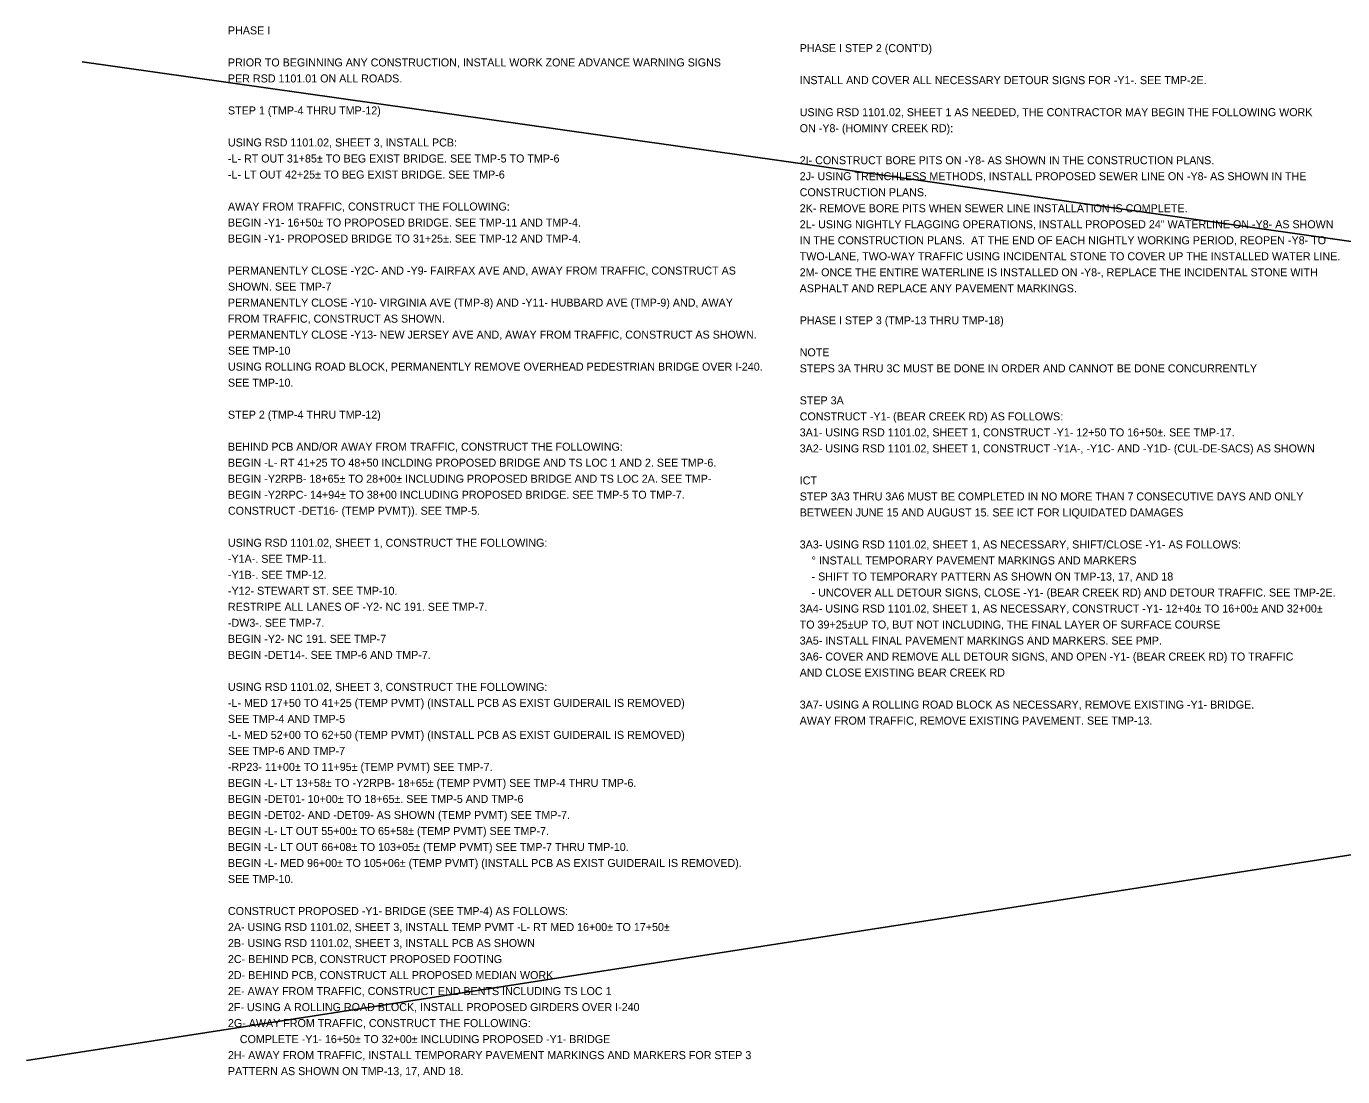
# Model space of a CAD drawing. Extents: x 2483905 to 2494512, y 366160 to 372330.
# Drawn here: x 2486863 to 2488014, y 371409 to 372328 of the extents above; entities that cross this region are included whole.
import ezdxf

# ---------------------------------------------------------------- set-up
doc = ezdxf.new("R2010")
doc.units = 0
doc.layers.add('TC SHEET BORDER LINE THIN', color=7, linetype='Continuous')

msp = doc.modelspace()

# ---------------------------------------------------------------- linework, layer by layer
at = {"layer": 'TC SHEET BORDER LINE THIN'}
for p, q in [((2486912.1, 372296.4), (2492000.8, 371577)), ((2486863.2, 371423.3), (2492035.7, 372226.5))]:
    msp.add_line(p, q, dxfattribs=at)

# ---------------------------------------------------------------- texts
for s, p in [('PHASE I', (2487039.5, 372320.5)), ("PHASE I STEP 2 (CONT'D)", (2487539.5, 372305)), ('PRIOR TO BEGINNING ANY CONSTRUCTION, INSTALL WORK ZONE ADVANCE WARNING SIGNS', (2487039.5, 372292.5)), ('PER RSD 1101.01 ON ALL ROADS.', (2487039.5, 372278.5)), ('INSTALL AND COVER ALL NECESSARY DETOUR SIGNS FOR -Y1-. SEE TMP-2E.', (2487539.5, 372277)), ('STEP 1 (TMP-4 THRU TMP-12)', (2487039.5, 372250.5)), ('USING RSD 1101.02, SHEET 1 AS NEEDED, THE CONTRACTOR MAY BEGIN THE FOLLOWING WORK', (2487539.5, 372249)), ('ON -Y8- (HOMINY CREEK RD):', (2487539.5, 372235)), ('USING RSD 1101.02, SHEET 3, INSTALL PCB:', (2487039.5, 372222.5)), ('-L- RT OUT 31+85± TO BEG EXIST BRIDGE. SEE TMP-5 TO TMP-6', (2487039.5, 372208.5)), ('2I- CONSTRUCT BORE PITS ON -Y8- AS SHOWN IN THE CONSTRUCTION PLANS.', (2487539.5, 372207)), ('-L- LT OUT 42+25± TO BEG EXIST BRIDGE. SEE TMP-6', (2487039.5, 372194.5)), ('2J- USING TRENCHLESS METHODS, INSTALL PROPOSED SEWER LINE ON -Y8- AS SHOWN IN THE', (2487539.5, 372193)), ('CONSTRUCTION PLANS.', (2487539.5, 372179)), ('AWAY FROM TRAFFIC, CONSTRUCT THE FOLLOWING:', (2487039.5, 372166.5)), ('2K- REMOVE BORE PITS WHEN SEWER LINE INSTALLATION IS COMPLETE.', (2487539.5, 372165)), ('BEGIN -Y1- 16+50± TO PROPOSED BRIDGE. SEE TMP-11 AND TMP-4.', (2487039.5, 372152.5)), ('2L- USING NIGHTLY FLAGGING OPERATIONS, INSTALL PROPOSED 24" WATERLINE ON -Y8- AS SHOWN', (2487539.5, 372151)), ('BEGIN -Y1- PROPOSED BRIDGE TO 31+25±. SEE TMP-12 AND TMP-4.', (2487039.5, 372138.5)), ('IN THE CONSTRUCTION PLANS.  AT THE END OF EACH NIGHTLY WORKING PERIOD, REOPEN -Y8- TO', (2487539.5, 372137)), ('TWO-LANE, TWO-WAY TRAFFIC USING INCIDENTAL STONE TO COVER UP THE INSTALLED WATER LINE.', (2487539.5, 372123)), ('PERMANENTLY CLOSE -Y2C- AND -Y9- FAIRFAX AVE AND, AWAY FROM TRAFFIC, CONSTRUCT AS', (2487039.5, 372110.5)), ('2M- ONCE THE ENTIRE WATERLINE IS INSTALLED ON -Y8-, REPLACE THE INCIDENTAL STONE WITH', (2487539.5, 372109)), ('SHOWN. SEE TMP-7', (2487039.5, 372096.5)), ('ASPHALT AND REPLACE ANY PAVEMENT MARKINGS.', (2487539.5, 372095)), ('PERMANENTLY CLOSE -Y10- VIRGINIA AVE (TMP-8) AND -Y11- HUBBARD AVE (TMP-9) AND, AWAY', (2487039.5, 372082.5)), ('FROM TRAFFIC, CONSTRUCT AS SHOWN. ', (2487039.5, 372068.5)), ('PHASE I STEP 3 (TMP-13 THRU TMP-18)', (2487539.5, 372067)), ('PERMANENTLY CLOSE -Y13- NEW JERSEY AVE AND, AWAY FROM TRAFFIC, CONSTRUCT AS SHOWN.', (2487039.5, 372054.5)), ('SEE TMP-10', (2487039.5, 372040.5)), ('NOTE', (2487539.5, 372039)), ('USING ROLLING ROAD BLOCK, PERMANENTLY REMOVE OVERHEAD PEDESTRIAN BRIDGE OVER I-240.', (2487039.5, 372026.5)), ('STEPS 3A THRU 3C MUST BE DONE IN ORDER AND CANNOT BE DONE CONCURRENTLY', (2487539.5, 372025)), ('SEE TMP-10.', (2487039.5, 372012.5)), ('STEP 3A', (2487539.5, 371997)), ('STEP 2 (TMP-4 THRU TMP-12)', (2487039.5, 371984.5)), ('CONSTRUCT -Y1- (BEAR CREEK RD) AS FOLLOWS:', (2487539.5, 371983)), ('3A1- USING RSD 1101.02, SHEET 1, CONSTRUCT -Y1- 12+50 TO 16+50±. SEE TMP-17.', (2487539.5, 371969)), ('BEHIND PCB AND/OR AWAY FROM TRAFFIC, CONSTRUCT THE FOLLOWING:', (2487039.5, 371956.5)), ('3A2- USING RSD 1101.02, SHEET 1, CONSTRUCT -Y1A-, -Y1C- AND -Y1D- (CUL-DE-SACS) AS SHOWN', (2487539.5, 371955)), ('BEGIN -L- RT 41+25 TO 48+50 INCLDING PROPOSED BRIDGE AND TS LOC 1 AND 2. SEE TMP-6.', (2487039.5, 371942.5)), ('BEGIN -Y2RPB- 18+65± TO 28+00± INCLUDING PROPOSED BRIDGE AND TS LOC 2A. SEE TMP-', (2487039.5, 371928.5)), ('ICT', (2487539.5, 371927)), ('BEGIN -Y2RPC- 14+94± TO 38+00 INCLUDING PROPOSED BRIDGE. SEE TMP-5 TO TMP-7.', (2487039.5, 371914.5)), ('STEP 3A3 THRU 3A6 MUST BE COMPLETED IN NO MORE THAN 7 CONSECUTIVE DAYS AND ONLY', (2487539.5, 371913)), ('CONSTRUCT -DET16- (TEMP PVMT)). SEE TMP-5.', (2487039.5, 371900.5)), ('BETWEEN JUNE 15 AND AUGUST 15. SEE ICT FOR LIQUIDATED DAMAGES', (2487539.5, 371899)), ('USING RSD 1101.02, SHEET 1, CONSTRUCT THE FOLLOWING:', (2487039.5, 371872.5)), ('3A3- USING RSD 1101.02, SHEET 1, AS NECESSARY, SHIFT/CLOSE -Y1- AS FOLLOWS:', (2487539.5, 371871)), ('-Y1A-. SEE TMP-11.', (2487039.5, 371858.5)), ('    ° INSTALL TEMPORARY PAVEMENT MARKINGS AND MARKERS', (2487539.5, 371857)), ('-Y1B-. SEE TMP-12.', (2487039.5, 371844.5)), ('    - SHIFT TO TEMPORARY PATTERN AS SHOWN ON TMP-13, 17, AND 18', (2487539.5, 371843)), ('-Y12- STEWART ST. SEE TMP-10.', (2487039.5, 371830.5)), ('    - UNCOVER ALL DETOUR SIGNS, CLOSE -Y1- (BEAR CREEK RD) AND DETOUR TRAFFIC. SEE TMP-2E.', (2487539.5, 371829)), ('RESTRIPE ALL LANES OF -Y2- NC 191. SEE TMP-7.', (2487039.5, 371816.5)), ('3A4- USING RSD 1101.02, SHEET 1, AS NECESSARY, CONSTRUCT -Y1- 12+40± TO 16+00± AND 32+00±', (2487539.5, 371815)), ('-DW3-. SEE TMP-7.', (2487039.5, 371802.5)), ('TO 39+25±UP TO, BUT NOT INCLUDING, THE FINAL LAYER OF SURFACE COURSE', (2487539.5, 371801)), ('BEGIN -Y2- NC 191. SEE TMP-7', (2487039.5, 371788.5)), ('3A5- INSTALL FINAL PAVEMENT MARKINGS AND MARKERS. SEE PMP.', (2487539.5, 371787)), ('BEGIN -DET14-. SEE TMP-6 AND TMP-7.', (2487039.5, 371774.5)), ('3A6- COVER AND REMOVE ALL DETOUR SIGNS, AND OPEN -Y1- (BEAR CREEK RD) TO TRAFFIC', (2487539.5, 371773)), ('AND CLOSE EXISTING BEAR CREEK RD', (2487539.5, 371759)), ('USING RSD 1101.02, SHEET 3, CONSTRUCT THE FOLLOWING:', (2487039.5, 371746.5)), ('-L- MED 17+50 TO 41+25 (TEMP PVMT) (INSTALL PCB AS EXIST GUIDERAIL IS REMOVED)', (2487039.5, 371732.5)), ('3A7- USING A ROLLING ROAD BLOCK AS NECESSARY, REMOVE EXISTING -Y1- BRIDGE.', (2487539.5, 371731)), ('SEE TMP-4 AND TMP-5', (2487039.5, 371718.5)), ('AWAY FROM TRAFFIC, REMOVE EXISTING PAVEMENT. SEE TMP-13.', (2487539.5, 371717)), ('-L- MED 52+00 TO 62+50 (TEMP PVMT) (INSTALL PCB AS EXIST GUIDERAIL IS REMOVED)', (2487039.5, 371704.5)), ('SEE TMP-6 AND TMP-7', (2487039.5, 371690.5)), ('-RP23- 11+00± TO 11+95± (TEMP PVMT) SEE TMP-7.', (2487039.5, 371676.5)), ('BEGIN -L- LT 13+58± TO -Y2RPB- 18+65± (TEMP PVMT) SEE TMP-4 THRU TMP-6.', (2487039.5, 371662.5)), ('BEGIN -DET01- 10+00± TO 18+65±. SEE TMP-5 AND TMP-6', (2487039.5, 371648.5)), ('BEGIN -DET02- AND -DET09- AS SHOWN (TEMP PVMT) SEE TMP-7.', (2487039.5, 371634.5)), ('BEGIN -L- LT OUT 55+00± TO 65+58± (TEMP PVMT) SEE TMP-7.', (2487039.5, 371620.5)), ('BEGIN -L- LT OUT 66+08± TO 103+05± (TEMP PVMT) SEE TMP-7 THRU TMP-10.', (2487039.5, 371606.5)), ('BEGIN -L- MED 96+00± TO 105+06± (TEMP PVMT) (INSTALL PCB AS EXIST GUIDERAIL IS REMOVED).', (2487039.5, 371592.5)), ('SEE TMP-10.', (2487039.5, 371578.5)), ('CONSTRUCT PROPOSED -Y1- BRIDGE (SEE TMP-4) AS FOLLOWS:', (2487039.5, 371550.5)), ('2A- USING RSD 1101.02, SHEET 3, INSTALL TEMP PVMT -L- RT MED 16+00± TO 17+50±', (2487039.5, 371536.5)), ('2B- USING RSD 1101.02, SHEET 3, INSTALL PCB AS SHOWN', (2487039.5, 371522.5)), ('2C- BEHIND PCB, CONSTRUCT PROPOSED FOOTING', (2487039.5, 371508.5)), ('2D- BEHIND PCB, CONSTRUCT ALL PROPOSED MEDIAN WORK', (2487039.5, 371494.5)), ('2E- AWAY FROM TRAFFIC, CONSTRUCT END BENTS INCLUDING TS LOC 1', (2487039.5, 371480.5)), ('2F- USING A ROLLING ROAD BLOCK, INSTALL PROPOSED GIRDERS OVER I-240', (2487039.5, 371466.5)), ('2G- AWAY FROM TRAFFIC, CONSTRUCT THE FOLLOWING:', (2487039.5, 371452.5)), ('    COMPLETE -Y1- 16+50± TO 32+00± INCLUDING PROPOSED -Y1- BRIDGE', (2487039.5, 371438.5)), ('2H- AWAY FROM TRAFFIC, INSTALL TEMPORARY PAVEMENT MARKINGS AND MARKERS FOR STEP 3', (2487039.5, 371424.5)), ('PATTERN AS SHOWN ON TMP-13, 17, AND 18.', (2487039.5, 371410.5))]:
    msp.add_text(s, height=7, dxfattribs=at).set_placement(p)

doc.saveas('drawing.dxf')
